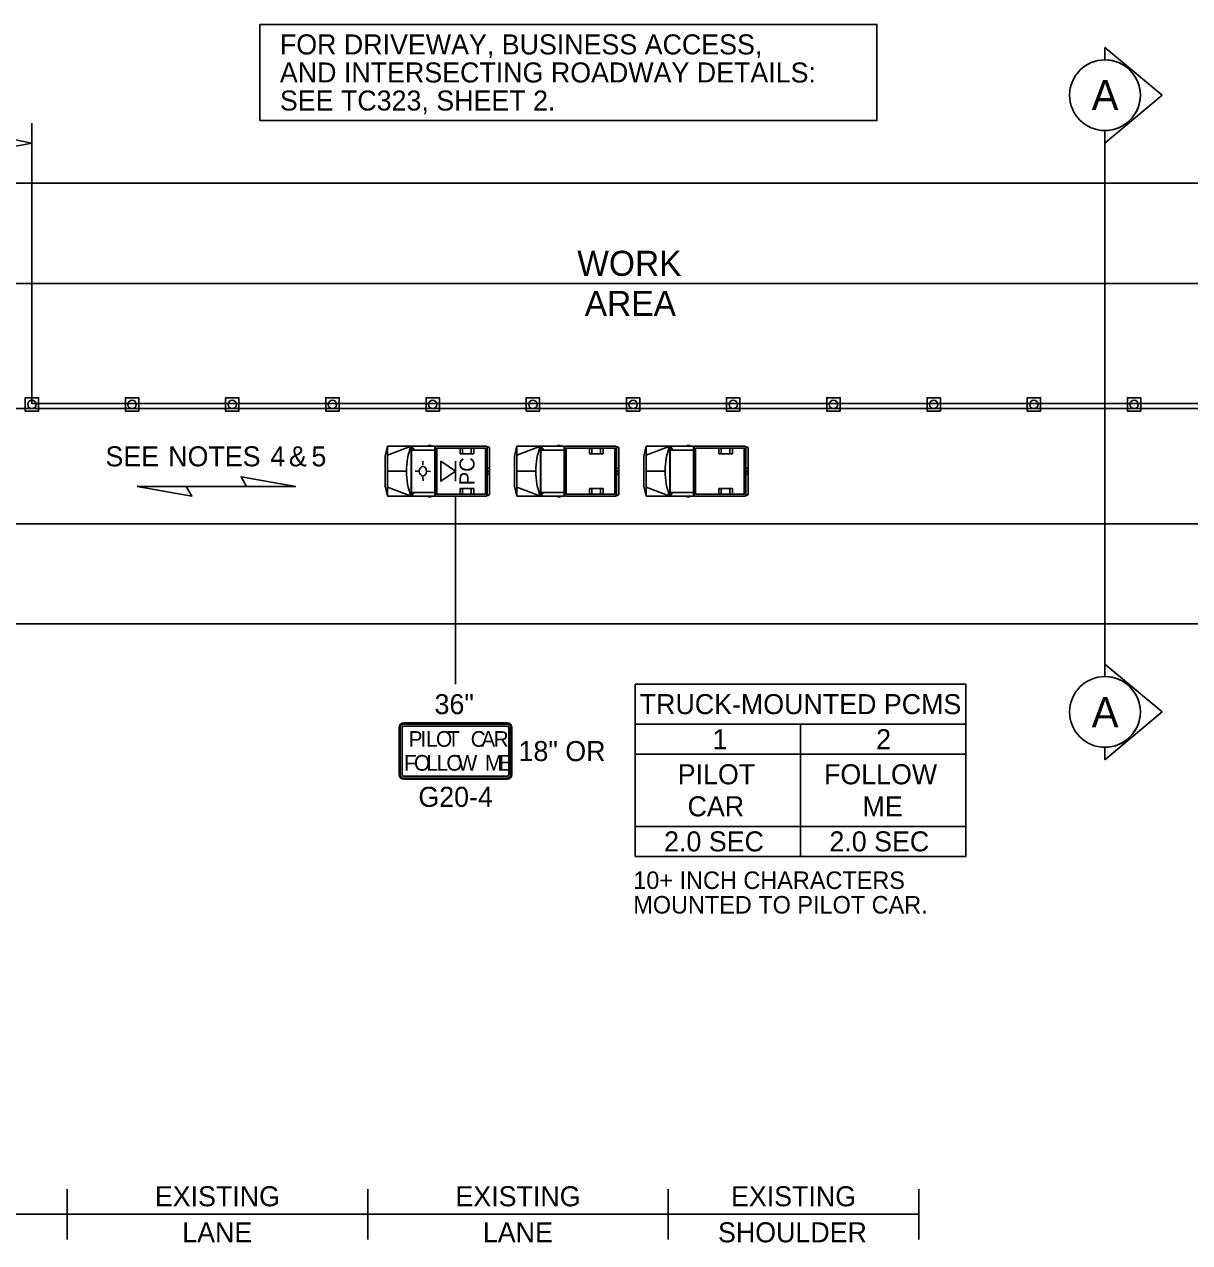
# Model space of a CAD drawing. Extents: x 99999.1 to 100095.7, y 99995 to 100010.7.
# Drawn here: x 100005.12 to 100009.772, y 100003.262 to 100008.126 of the extents above; entities that cross this region are included whole.
import ezdxf

# ---------------------------------------------------------------- set-up
doc = ezdxf.new("R2010")
doc.units = 0
for name, color, linetype in [('RD_ED_ShoulderPavedEdge', 7, 'Continuous'), ('RD_MK_LineEdgeWhite', 7, 'Continuous'), ('RD_MK_LineSkipCenter', 7, 'Continuous'), ('SH_TI_Tables', 7, 'Continuous'), ('SH_TI_WZSectionCut', 7, 'Continuous'), ('TR_SN_ConstructionSigns', 7, 'Continuous'), ('TR_WZ_MotoristVehicle', 7, 'Continuous'), ('TR_WZ_PortableChangeMessageSign', 7, 'Continuous'), ('TR_WZ_PortableSignMountBlk-Wht', 7, 'Continuous'), ('TR_WZ_TrafficCone', 7, 'Continuous'), ('TR_WZ_WorkAreaLabel', 7, 'Continuous'), ('TR_WZ_WorkZoneDetails', 7, 'Continuous'), ('TR_WZ_WorkZoneTextCurrent', 7, 'Continuous')]:
    doc.layers.add(name, color=color, linetype=linetype)

msp = doc.modelspace()

# ---------------------------------------------------------------- linework, layer by layer
at = {"layer": 'RD_ED_ShoulderPavedEdge'}
for p, q in [((100000.1076, 100007.4923), (100015.6424, 100007.4923)), ((100000.1076, 100005.7323), (100015.6424, 100005.7323))]:
    msp.add_line(p, q, dxfattribs=at)
at = {"layer": 'RD_MK_LineEdgeWhite'}
for p, q in [((100000.1076, 100007.0923), (100015.6424, 100007.0923)), ((100000.1076, 100006.1323), (100015.6424, 100006.1323))]:
    msp.add_line(p, q, dxfattribs=at)
at = {"layer": 'RD_MK_LineSkipCenter'}
msp.add_lwpolyline([(100011.15, 100006.5923), (100003.4767, 100006.5923)], dxfattribs=at)
at = {"layer": 'SH_TI_Tables'}
msp.add_lwpolyline([(100006.0601, 100008.1263), (100008.5236, 100008.1263), (100008.5236, 100007.7423), (100006.0601, 100007.7423)], close=True, dxfattribs=at)
at = {"layer": 'SH_TI_WZSectionCut'}
for p, q in [((100009.4337, 100007.9847), (100009.4337, 100008.0346)), ((100009.4337, 100008.0346), (100009.6619, 100007.8435)), ((100009.6619, 100007.8435), (100009.4337, 100007.6523)), ((100009.4337, 100007.6523), (100009.4337, 100007.7022)), ((100009.4338, 100007.7022), (100009.4338, 100005.5723)), ((100009.4337, 100005.5723), (100009.4337, 100005.5224)), ((100009.6619, 100005.3812), (100009.4337, 100005.5723)), ((100009.4337, 100005.1901), (100009.6619, 100005.3812)), ((100009.4337, 100005.24), (100009.4337, 100005.1901))]:
    msp.add_line(p, q, dxfattribs=at)
for centre in [(100009.4338, 100007.8435), (100009.4338, 100005.3812)]:
    msp.add_circle(centre, 0.1412, dxfattribs=at)
for centre in [(100009.4338, 100007.8435), (100009.4338, 100005.3812)]:
    msp.add_arc(centre, 0.1412, 269.9978, 90.0022, dxfattribs=at)
at = {"layer": 'TR_SN_ConstructionSigns'}
for p, q in [((100006.6159, 100005.3186), (100006.6159, 100005.1311)), ((100006.6206, 100005.3186), (100006.6206, 100005.3186)), ((100006.6206, 100005.3186), (100006.6206, 100005.1311)), ((100006.6284, 100005.1311), (100006.6284, 100005.3186)), ((100007.0472, 100005.3373), (100006.6347, 100005.3373)), ((100007.0472, 100005.3326), (100006.6347, 100005.3326)), ((100006.6347, 100005.3248), (100007.0472, 100005.3248)), ((100007.0472, 100005.3326), (100007.0472, 100005.3326)), ((100007.0534, 100005.3186), (100007.0534, 100005.1311)), ((100007.0612, 100005.1311), (100007.0612, 100005.3186)), ((100007.0659, 100005.1311), (100007.0659, 100005.3186)), ((100007.0472, 100005.1248), (100006.6347, 100005.1248)), ((100006.6347, 100005.117), (100006.6347, 100005.117)), ((100006.6347, 100005.117), (100007.0472, 100005.117)), ((100006.6347, 100005.1123), (100007.0472, 100005.1123)), ((100007.0612, 100005.1311), (100007.0612, 100005.1311))]:
    msp.add_line(p, q, dxfattribs=at)
for centre, radius, start, end in [((100006.6347, 100005.3186), 0.0187, 90, 180), ((100006.6347, 100005.3186), 0.0141, 90, 180), ((100006.6347, 100005.3186), 0.00625, 90, 180), ((100007.0472, 100005.3186), 0.0187, 0, 90), ((100007.0472, 100005.3186), 0.0141, 0, 90), ((100007.0472, 100005.3186), 0.00625, 0, 90), ((100006.6347, 100005.1311), 0.0187, 180, 270), ((100006.6347, 100005.1311), 0.0141, 180, 270), ((100006.6347, 100005.1311), 0.00625, 180, 270), ((100007.0472, 100005.1311), 0.0141, 270, 0), ((100007.0472, 100005.1311), 0.00625, 270, 0), ((100007.0472, 100005.1311), 0.0187, 270, 0)]:
    msp.add_arc(centre, radius, start, end, dxfattribs=at)
at = {"layer": 'TR_WZ_MotoristVehicle'}
for p, q in [((100006.5693, 100006.4423), (100006.56, 100006.402)), ((100006.5693, 100006.4423), (100006.5693, 100006.2423)), ((100006.5693, 100006.4423), (100006.7582, 100006.4423)), ((100006.5693, 100006.4057), (100006.6638, 100006.4423)), ((100006.6638, 100006.4423), (100006.6638, 100006.2423)), ((100006.6655, 100006.4423), (100006.6655, 100006.2423)), ((100006.6655, 100006.4423), (100006.6775, 100006.4268)), ((100006.6655, 100006.4268), (100006.7582, 100006.4268)), ((100006.7324, 100006.4451), (100006.7438, 100006.4451)), ((100006.7582, 100006.4423), (100006.7582, 100006.2423)), ((100006.9667, 100006.4423), (100006.761, 100006.4423)), ((100006.761, 100006.4423), (100006.761, 100006.2423)), ((100006.9608, 100006.4344), (100006.7668, 100006.4344)), ((100006.7668, 100006.4344), (100006.7668, 100006.2503)), ((100006.8595, 100006.4344), (100006.8595, 100006.4113)), ((100006.8695, 100006.4344), (100006.8695, 100006.4113)), ((100006.9035, 100006.4344), (100006.9035, 100006.4113)), ((100006.9145, 100006.4344), (100006.9145, 100006.4113)), ((100006.9608, 100006.4344), (100006.9608, 100006.2503)), ((100006.9667, 100006.4423), (100006.9667, 100006.2423)), ((100006.9718, 100006.439), (100006.9674, 100006.439)), ((100006.9674, 100006.439), (100006.9674, 100006.2456)), ((100006.9763, 100006.4329), (100006.9763, 100006.2517)), ((100007.0856, 100006.4423), (100007.0763, 100006.402)), ((100007.0856, 100006.4423), (100007.0856, 100006.2423)), ((100007.0856, 100006.4423), (100007.2745, 100006.4423)), ((100007.0856, 100006.4057), (100007.18, 100006.4423)), ((100007.18, 100006.4423), (100007.18, 100006.2423)), ((100007.1817, 100006.4423), (100007.1817, 100006.2423)), ((100007.1817, 100006.4423), (100007.1938, 100006.4268)), ((100007.1817, 100006.4268), (100007.2745, 100006.4268)), ((100007.2487, 100006.4451), (100007.26, 100006.4451)), ((100007.2745, 100006.4423), (100007.2745, 100006.2423)), ((100007.4829, 100006.4423), (100007.2772, 100006.4423)), ((100007.2772, 100006.4423), (100007.2772, 100006.2423)), ((100007.4771, 100006.4344), (100007.2831, 100006.4344)), ((100007.2831, 100006.4344), (100007.2831, 100006.2503)), ((100007.3758, 100006.4344), (100007.3758, 100006.4113)), ((100007.3857, 100006.4344), (100007.3857, 100006.4113)), ((100007.4197, 100006.4344), (100007.4197, 100006.4113)), ((100007.4307, 100006.4344), (100007.4307, 100006.4113)), ((100007.4771, 100006.4344), (100007.4771, 100006.2503)), ((100007.4829, 100006.4423), (100007.4829, 100006.2423)), ((100007.4881, 100006.439), (100007.4836, 100006.439)), ((100007.4836, 100006.439), (100007.4836, 100006.2456)), ((100007.4926, 100006.4329), (100007.4926, 100006.2517)), ((100007.6018, 100006.4423), (100007.5926, 100006.402)), ((100007.6018, 100006.4423), (100007.6018, 100006.2423)), ((100007.6018, 100006.4423), (100007.7907, 100006.4423)), ((100007.6018, 100006.4057), (100007.6963, 100006.4423)), ((100007.6963, 100006.4423), (100007.6963, 100006.2423)), ((100007.698, 100006.4423), (100007.698, 100006.2423)), ((100007.698, 100006.4423), (100007.71, 100006.4268)), ((100007.698, 100006.4268), (100007.7907, 100006.4268)), ((100007.765, 100006.4451), (100007.7763, 100006.4451)), ((100007.7907, 100006.4423), (100007.7907, 100006.2423)), ((100007.9992, 100006.4423), (100007.7935, 100006.4423)), ((100007.7935, 100006.4423), (100007.7935, 100006.2423)), ((100007.9934, 100006.4344), (100007.7993, 100006.4344)), ((100007.7993, 100006.4344), (100007.7993, 100006.2503)), ((100007.892, 100006.4344), (100007.892, 100006.4113)), ((100007.902, 100006.4344), (100007.902, 100006.4113)), ((100007.936, 100006.4344), (100007.936, 100006.4113)), ((100007.947, 100006.4344), (100007.947, 100006.4113)), ((100007.9934, 100006.4344), (100007.9934, 100006.2503)), ((100007.9992, 100006.4423), (100007.9992, 100006.2423)), ((100008.0044, 100006.439), (100007.9999, 100006.439)), ((100007.9999, 100006.439), (100007.9999, 100006.2456)), ((100008.0088, 100006.4329), (100008.0088, 100006.2517)), ((100006.56, 100006.402), (100006.56, 100006.2827)), ((100006.7108, 100006.382), (100006.7108, 100006.3658)), ((100006.9145, 100006.4113), (100006.8595, 100006.4113)), ((100007.0763, 100006.402), (100007.0763, 100006.2827)), ((100007.4307, 100006.4113), (100007.3758, 100006.4113)), ((100007.5926, 100006.402), (100007.5926, 100006.2827)), ((100007.947, 100006.4113), (100007.892, 100006.4113)), ((100006.5693, 100006.3423), (100006.6452, 100006.3423)), ((100006.6807, 100006.3425), (100006.6933, 100006.3424)), ((100006.7249, 100006.342), (100006.7249, 100006.342)), ((100006.7417, 100006.3416), (100006.7268, 100006.3419)), ((100006.9763, 100006.3564), (100006.9674, 100006.3527)), ((100006.9763, 100006.3282), (100006.9674, 100006.332)), ((100006.9739, 100006.3423), (100006.9698, 100006.3423)), ((100006.9718, 100006.3451), (100006.9718, 100006.3395)), ((100007.0856, 100006.3423), (100007.1615, 100006.3423)), ((100007.4926, 100006.3564), (100007.4836, 100006.3527)), ((100007.4926, 100006.3282), (100007.4836, 100006.332)), ((100007.4902, 100006.3423), (100007.486, 100006.3423)), ((100007.4881, 100006.3451), (100007.4881, 100006.3395)), ((100007.6018, 100006.3423), (100007.6777, 100006.3423)), ((100008.0088, 100006.3564), (100007.9999, 100006.3527)), ((100008.0088, 100006.3282), (100007.9999, 100006.332)), ((100008.0064, 100006.3423), (100008.0023, 100006.3423)), ((100008.0044, 100006.3451), (100008.0044, 100006.3395)), ((100006.5693, 100006.2423), (100006.56, 100006.2827)), ((100006.5693, 100006.279), (100006.6638, 100006.2423)), ((100006.7115, 100006.3039), (100006.7112, 100006.3189)), ((100007.0856, 100006.2423), (100007.0763, 100006.2827)), ((100007.0856, 100006.279), (100007.18, 100006.2423)), ((100007.6018, 100006.2423), (100007.5926, 100006.2827)), ((100007.6018, 100006.279), (100007.6963, 100006.2423)), ((100006.5693, 100006.2423), (100006.7582, 100006.2423)), ((100006.6655, 100006.2578), (100006.7582, 100006.2578)), ((100006.6754, 100006.2578), (100006.6655, 100006.2423)), ((100006.7324, 100006.2395), (100006.7438, 100006.2395)), ((100006.9667, 100006.2423), (100006.761, 100006.2423)), ((100006.9608, 100006.2503), (100006.7668, 100006.2503)), ((100006.8595, 100006.2503), (100006.8595, 100006.2733)), ((100006.9145, 100006.2733), (100006.8595, 100006.2733)), ((100006.8695, 100006.2503), (100006.8695, 100006.2733)), ((100006.9035, 100006.2503), (100006.9035, 100006.2733)), ((100006.9145, 100006.2503), (100006.9145, 100006.2733)), ((100006.9718, 100006.2456), (100006.9674, 100006.2456)), ((100007.0856, 100006.2423), (100007.2745, 100006.2423)), ((100007.1817, 100006.2578), (100007.2745, 100006.2578)), ((100007.1917, 100006.2578), (100007.1817, 100006.2423)), ((100007.2487, 100006.2395), (100007.26, 100006.2395)), ((100007.4829, 100006.2423), (100007.2772, 100006.2423)), ((100007.4771, 100006.2503), (100007.2831, 100006.2503)), ((100007.3758, 100006.2503), (100007.3758, 100006.2733)), ((100007.4307, 100006.2733), (100007.3758, 100006.2733)), ((100007.3857, 100006.2503), (100007.3857, 100006.2733)), ((100007.4197, 100006.2503), (100007.4197, 100006.2733)), ((100007.4307, 100006.2503), (100007.4307, 100006.2733)), ((100007.4881, 100006.2456), (100007.4836, 100006.2456)), ((100007.6018, 100006.2423), (100007.7907, 100006.2423)), ((100007.698, 100006.2578), (100007.7907, 100006.2578)), ((100007.708, 100006.2578), (100007.698, 100006.2423)), ((100007.765, 100006.2395), (100007.7763, 100006.2395)), ((100007.9992, 100006.2423), (100007.7935, 100006.2423)), ((100007.9934, 100006.2503), (100007.7993, 100006.2503)), ((100007.892, 100006.2503), (100007.892, 100006.2733)), ((100007.947, 100006.2733), (100007.892, 100006.2733)), ((100007.902, 100006.2503), (100007.902, 100006.2733)), ((100007.936, 100006.2503), (100007.936, 100006.2733)), ((100007.947, 100006.2503), (100007.947, 100006.2733)), ((100008.0044, 100006.2456), (100007.9999, 100006.2456))]:
    msp.add_line(p, q, dxfattribs=at)
for centre, major_axis, start_param, end_param in [((100006.7987, 100006.3423), (0, -0.2099), 4.215667, 5.208926), ((100006.9718, 100006.4329), (0, 0.0061), 4.712389, 6.283185), ((100007.315, 100006.3423), (0, -0.2099), 4.215667, 5.208926), ((100007.4881, 100006.4329), (0, 0.0061), 4.712389, 6.283185), ((100007.8313, 100006.3423), (0, -0.2099), 4.215667, 5.208926), ((100008.0044, 100006.4329), (0, 0.0061), 4.712389, 6.283185), ((100006.9718, 100006.2517), (0, -0.0061), 0, 1.570796), ((100007.4881, 100006.2517), (0, -0.0061), 0, 1.570796), ((100008.0044, 100006.2517), (0, -0.0061), 0, 1.570796)]:
    msp.add_ellipse(centre, major_axis=major_axis, ratio=0.73155, start_param=start_param, end_param=end_param, dxfattribs=at)
for centre, major_axis in [((100006.7108, 100006.3423), (0, 0.0193)), ((100006.9718, 100006.3423), (0, 0.00282)), ((100007.4881, 100006.3423), (0, 0.00282)), ((100008.0044, 100006.3423), (0, 0.00282))]:
    msp.add_ellipse(centre, major_axis=major_axis, ratio=0.73155, dxfattribs=at)
at = {"layer": 'TR_WZ_PortableChangeMessageSign'}
for p, q in [((100007.5582, 100005.4923), (100008.8782, 100005.4923)), ((100007.5582, 100004.8043), (100007.5582, 100005.4923)), ((100008.8782, 100004.8043), (100008.8782, 100005.4923)), ((100008.8782, 100005.3323), (100007.5582, 100005.3323)), ((100008.2182, 100004.8043), (100008.2182, 100005.3323)), ((100008.2182, 100005.2123), (100007.5582, 100005.2123)), ((100008.8782, 100005.2123), (100008.2182, 100005.2123)), ((100007.5582, 100004.9243), (100008.2182, 100004.9243)), ((100008.2182, 100004.9243), (100008.8782, 100004.9243)), ((100008.8782, 100004.8043), (100007.5582, 100004.8043))]:
    msp.add_line(p, q, dxfattribs=at)
at = {"layer": 'TR_WZ_PortableSignMountBlk-Wht'}
msp.add_line((100006.8406, 100006.3822), (100006.8406, 100006.3022), dxfattribs=at)
msp.add_lwpolyline([(100006.8406, 100006.3423), (100006.7832, 100006.3022), (100006.7832, 100006.3822)], close=True, dxfattribs=at)
at = {"layer": 'TR_WZ_TrafficCone'}
for points in [[(100005.1234, 100006.6357), (100005.1767, 100006.6357), (100005.1767, 100006.5823), (100005.1234, 100006.5823), (100005.1234, 100006.6357)], [(100005.1234, 100006.5823), (100005.1767, 100006.5823), (100005.1767, 100006.6357), (100005.1234, 100006.6357), (100005.1234, 100006.5823)], [(100005.5234, 100006.6357), (100005.5767, 100006.6357), (100005.5767, 100006.5823), (100005.5234, 100006.5823), (100005.5234, 100006.6357)], [(100005.5234, 100006.5823), (100005.5767, 100006.5823), (100005.5767, 100006.6357), (100005.5234, 100006.6357), (100005.5234, 100006.5823)], [(100005.9234, 100006.6357), (100005.9767, 100006.6357), (100005.9767, 100006.5823), (100005.9234, 100006.5823), (100005.9234, 100006.6357)], [(100005.9234, 100006.5823), (100005.9767, 100006.5823), (100005.9767, 100006.6357), (100005.9234, 100006.6357), (100005.9234, 100006.5823)], [(100006.3234, 100006.6357), (100006.3767, 100006.6357), (100006.3767, 100006.5823), (100006.3234, 100006.5823), (100006.3234, 100006.6357)], [(100006.3234, 100006.5823), (100006.3767, 100006.5823), (100006.3767, 100006.6357), (100006.3234, 100006.6357), (100006.3234, 100006.5823)], [(100006.7234, 100006.6357), (100006.7767, 100006.6357), (100006.7767, 100006.5823), (100006.7234, 100006.5823), (100006.7234, 100006.6357)], [(100006.7234, 100006.5823), (100006.7767, 100006.5823), (100006.7767, 100006.6357), (100006.7234, 100006.6357), (100006.7234, 100006.5823)], [(100007.1234, 100006.6357), (100007.1767, 100006.6357), (100007.1767, 100006.5823), (100007.1234, 100006.5823), (100007.1234, 100006.6357)], [(100007.1234, 100006.5823), (100007.1767, 100006.5823), (100007.1767, 100006.6357), (100007.1234, 100006.6357), (100007.1234, 100006.5823)], [(100007.5234, 100006.6357), (100007.5767, 100006.6357), (100007.5767, 100006.5823), (100007.5234, 100006.5823), (100007.5234, 100006.6357)], [(100007.5234, 100006.5823), (100007.5767, 100006.5823), (100007.5767, 100006.6357), (100007.5234, 100006.6357), (100007.5234, 100006.5823)], [(100007.9234, 100006.6357), (100007.9767, 100006.6357), (100007.9767, 100006.5823), (100007.9234, 100006.5823), (100007.9234, 100006.6357)], [(100007.9234, 100006.5823), (100007.9767, 100006.5823), (100007.9767, 100006.6357), (100007.9234, 100006.6357), (100007.9234, 100006.5823)], [(100008.3234, 100006.6357), (100008.3767, 100006.6357), (100008.3767, 100006.5823), (100008.3234, 100006.5823), (100008.3234, 100006.6357)], [(100008.3234, 100006.5823), (100008.3767, 100006.5823), (100008.3767, 100006.6357), (100008.3234, 100006.6357), (100008.3234, 100006.5823)], [(100008.7234, 100006.6357), (100008.7767, 100006.6357), (100008.7767, 100006.5823), (100008.7234, 100006.5823), (100008.7234, 100006.6357)], [(100008.7234, 100006.5823), (100008.7767, 100006.5823), (100008.7767, 100006.6357), (100008.7234, 100006.6357), (100008.7234, 100006.5823)], [(100009.1234, 100006.6357), (100009.1767, 100006.6357), (100009.1767, 100006.5823), (100009.1234, 100006.5823), (100009.1234, 100006.6357)], [(100009.1234, 100006.5823), (100009.1767, 100006.5823), (100009.1767, 100006.6357), (100009.1234, 100006.6357), (100009.1234, 100006.5823)], [(100009.5234, 100006.6357), (100009.5767, 100006.6357), (100009.5767, 100006.5823), (100009.5234, 100006.5823), (100009.5234, 100006.6357)], [(100009.5234, 100006.5823), (100009.5767, 100006.5823), (100009.5767, 100006.6357), (100009.5234, 100006.6357), (100009.5234, 100006.5823)]]:
    msp.add_lwpolyline(points, dxfattribs=at)
for centre in [(100005.15, 100006.609), (100005.55, 100006.609), (100005.95, 100006.609), (100006.35, 100006.609), (100006.75, 100006.609), (100007.15, 100006.609), (100007.55, 100006.609), (100007.95, 100006.609), (100008.35, 100006.609), (100008.75, 100006.609), (100009.15, 100006.609), (100009.55, 100006.609)]:
    msp.add_circle(centre, 0.0167, dxfattribs=at)
at = {"layer": 'TR_WZ_WorkZoneDetails'}
for p, q in [((100005.15, 100007.4923), (100005.15, 100007.7323)), ((100005.7663, 100006.2816), (100006.0074, 100006.2816)), ((100006.0074, 100006.2816), (100005.7663, 100006.2816)), ((100006.8406, 100006.2423), (100006.8406, 100005.4923)), ((100005.2907, 100003.2755), (100005.2907, 100003.4755)), ((100006.4907, 100003.2755), (100006.4907, 100003.4755)), ((100007.6907, 100003.2755), (100007.6907, 100003.4755)), ((100008.6907, 100003.2755), (100008.6907, 100003.4755)), ((100004.2907, 100003.3755), (100005.2907, 100003.3755)), ((100005.2907, 100003.3755), (100006.4907, 100003.3755)), ((100006.4907, 100003.3755), (100007.6907, 100003.3755)), ((100007.6907, 100003.3755), (100008.6907, 100003.3755))]:
    msp.add_line(p, q, dxfattribs=at)
for points in [[(100005.15, 100007.6523), (100005.0517, 100007.6331), (100005.0563, 100007.6523), (100005.0517, 100007.6716)], [(100005.15, 100007.4923), (100005.15, 100006.6123), (100009.9338, 100006.6123), (100009.9338, 100007.4923)], [(100005.5698, 100006.2816), (100005.7886, 100006.243), (100005.7663, 100006.2816)], [(100006.2039, 100006.2816), (100005.9851, 100006.3202), (100006.0074, 100006.2816)]]:
    msp.add_lwpolyline(points, close=True, dxfattribs=at)

# ---------------------------------------------------------------- texts
at = {"layer": 'SH_TI_Tables'}
for s, p in [('FOR DRIVEWAY, BUSINESS ACCESS,', (100006.1401, 100008.0063)), ('AND INTERSECTING ROADWAY DETAILS:', (100006.1401, 100007.8943)), ('SEE TC323, SHEET 2.', (100006.1401, 100007.7823))]:
    msp.add_text(s, height=0.08, rotation=360, dxfattribs=at).set_placement(p)
at = {"layer": 'SH_TI_WZSectionCut'}
for rotation, p in [(359.99, (100009.3808, 100007.7843)), (0.01, (100009.3808, 100005.3203))]:
    msp.add_text('A', height=0.12, rotation=rotation, dxfattribs=at).set_placement(p)
at = {"layer": 'TR_SN_ConstructionSigns'}
for s, p in [('36"', (100006.7575, 100005.3723)), ('18" OR', (100007.0928, 100005.1848)), ('G20-4', (100006.6929, 100005.0023))]:
    msp.add_text(s, height=0.08, rotation=360, dxfattribs=at).set_placement(p)
for s, p in [('P', (100006.6537, 100005.242)), ('I', (100006.7012, 100005.242)), ('L', (100006.7237, 100005.242)), ('O', (100006.7631, 100005.242)), ('T', (100006.8075, 100005.242)), ('C', (100006.9018, 100005.242)), ('A', (100006.9443, 100005.242)), ('R', (100006.9931, 100005.242)), ('F', (100006.6359, 100005.1467)), ('O', (100006.6753, 100005.1467)), ('L', (100006.7247, 100005.1467)), ('L', (100006.7653, 100005.1467)), ('O', (100006.8047, 100005.1467)), ('W', (100006.849, 100005.1467)), ('M', (100006.959, 100005.1467)), ('E', (100007.014, 100005.1467))]:
    msp.add_text(s, height=0.0625, dxfattribs=at).set_placement(p)
at = {"layer": 'TR_WZ_MotoristVehicle'}
msp.add_text('PC', height=0.06, rotation=90, dxfattribs=at).set_placement((100006.917, 100006.2863))
at = {"layer": 'TR_WZ_PortableChangeMessageSign'}
for s, height, p in [('TRUCK-MOUNTED PCMS', 0.08, (100007.5765, 100005.3723)), ('1', 0.08, (100007.8671, 100005.2323)), ('2', 0.08, (100008.5203, 100005.2323)), ('PILOT', 0.08, (100007.7283, 100005.0923)), ('FOLLOW', 0.08, (100008.3121, 100005.0923)), ('CAR', 0.08, (100007.7675, 100004.9643)), ('ME', 0.08, (100008.466, 100004.9643)), ('2.0 SEC', 0.08, (100007.6738, 100004.8243)), ('2.0 SEC', 0.08, (100008.3338, 100004.8243)), ('10+ INCH CHARACTERS', 0.07, (100007.5507, 100004.6743)), ('MOUNTED TO PILOT CAR.', 0.07, (100007.5507, 100004.5763))]:
    msp.add_text(s, height=height, rotation=360, dxfattribs=at).set_placement(p)
at = {"layer": 'TR_WZ_WorkAreaLabel'}
for s, p in [('WORK', (100007.3273, 100007.1223)), ('AREA', (100007.357, 100006.9623))]:
    msp.add_text(s, height=0.1, dxfattribs=at).set_placement(p)
at = {"layer": 'TR_WZ_WorkZoneDetails'}
for s, p in [('EXISTING', (100005.6409, 100003.4075)), ('EXISTING', (100006.8409, 100003.4075)), ('EXISTING', (100007.9409, 100003.4075)), ('LANE', (100005.7503, 100003.2635)), ('LANE', (100006.9503, 100003.2635)), ('SHOULDER', (100007.889, 100003.2635))]:
    msp.add_text(s, height=0.08, rotation=360, dxfattribs=at).set_placement(p)
at = {"layer": 'TR_WZ_WorkZoneTextCurrent'}
for s, p in [('SEE', (100005.4437, 100006.3616)), ('NOTES', (100005.6943, 100006.3616)), ('4', (100006.1018, 100006.3616)), ('&', (100006.1762, 100006.3616)), ('5', (100006.266, 100006.3616))]:
    msp.add_text(s, height=0.08, dxfattribs=at).set_placement(p)

doc.saveas('drawing.dxf')
